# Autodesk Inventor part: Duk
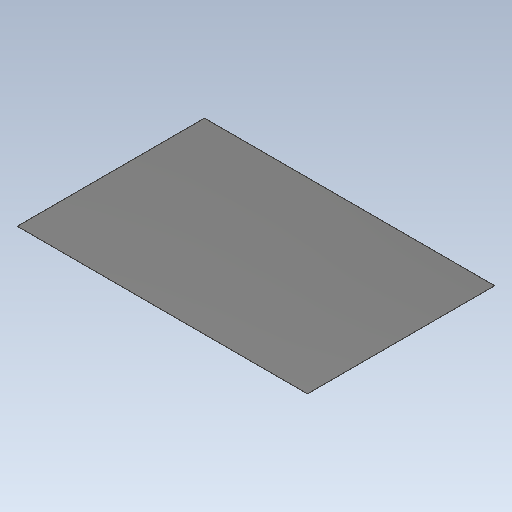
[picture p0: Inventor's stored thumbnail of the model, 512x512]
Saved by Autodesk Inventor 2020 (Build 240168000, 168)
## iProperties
Created: 2019-06
Part Number: Duk
Material: Acetal Resin, Black
Document SubType Name: Modeling
Designer: cl
Density: 1.425 g/cm^3
Appearance: Smooth - Black
Author: cl
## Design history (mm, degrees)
sketch "Sketch1"
  geometry: L1 (0, 0)-(3444, 0); L2 (3444, 0)-(3444, -2222); L3 (3444, -2222)-(0, -2222); L4 (0, -2222)-(0, 0)
  constraints: 8 end point, 2 parallel, 1 horizontal, 1 perpendicular
  dimensions: "d0" = 3444 distance of L2.end L3.end (computed from Daghöjd); "d1" = 2222 distance of L3.end L1.start (= Dagbredd)
extrude "Extrusion1" new body sketch "Sketch1" distance "d2" = 1.5; taper "d3" = 0 deg
body "Solid1"
other parameters: "Daghöjd" = 3254, "Dagbredd" = 2222
